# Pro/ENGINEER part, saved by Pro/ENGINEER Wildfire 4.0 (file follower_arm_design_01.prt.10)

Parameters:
  METRIC = "NO"

Other parameters: PITCH, DRILL_DIAMETER, THREAD_DIAMETER, THREADS_PER_INCH, THREAD_DEPTH, THREAD_LENGTH, DRILL_POINT_ANGLE, DRILL_DEPTH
